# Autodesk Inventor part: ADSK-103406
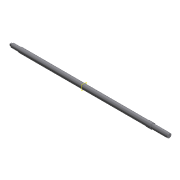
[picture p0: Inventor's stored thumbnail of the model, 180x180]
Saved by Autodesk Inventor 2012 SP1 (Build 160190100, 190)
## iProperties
Shininess: 0.0
Created: 2000-09
Part Number: ADSK-103406
Document SubType Name: Modeling
Stock Number: ADSK-103406
Density: 1 g/cm^3
Material: Default
Density: 0.0
Volumn: 0.0
Area: 0.0
PropertySet Name: Model Information
Control State: 0
Master: False
Checked Out: False
Author: gao
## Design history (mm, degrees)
node "Revolution1" dims "d20" = 360 deg
  sketch "Sketch1"
    geometry: L1 (-19.723, 10.363)-(1986.877, 10.363); L2 (1986.877, -26.943)-(-19.723, -26.943); L3 (-19.723, 4.807)-(-19.723, 10.363); L4 (1986.877, 10.363)-(1986.877, 14.332); L5 (1986.877, 14.332)-(2066.125, 14.332); L6 (2066.125, 14.332)-(2066.125, 8.057); L7 (2066.125, 8.057)-(2091.525, 8.057); L8 (2091.525, 8.057)-(2091.525, 7.855); L9 (2091.525, 7.855)-(2302.125, 7.855); L10 (2302.125, 7.855)-(2302.125, 5.557); L11 (2327.855, 5.557)-(2327.855, -26.943); L12 (1986.877, -26.943)-(2327.855, -26.943); L13 (2320.125, 5.557)-(2320.125, 4.057); L14 (2320.125, 4.057)-(2322.775, 4.057); L15 (2322.775, 4.057)-(2322.775, 5.557); L16 (2302.125, 5.557)-(2320.125, 5.557); L17 (2322.775, 5.557)-(2327.855, 5.557); L18 (-19.723, 4.807)-(-143.675, 4.807); L19 (-143.675, 4.807)-(-143.675, -26.943); L20 (-19.723, -26.943)-(-143.675, -26.943)
    constraints: 40 end point, 11 parallel, 8 perpendicular, 1 horizontal
    dimensions: "d1" = 37.30625 distance of L2.end L1.start; "d2" = 41.275 distance between parallel lines of L12 L5; "d4" = 79.248 distance of L4.end L5.end; "d5" = 25.4 distance of L6.end L7.end; "d6" = 35 distance between parallel lines of L12 L7; "d7" = 34.798 distance between parallel lines of L12 L9; "d9" = 32.5 distance between parallel lines of L12 L16; "d10" = 32.5 distance between parallel lines of L12 L17; "d11" = 31 distance between parallel lines of L12 L14; "d12" = 2.65 distance of L13.end L14.end; "d14" = 18 distance of L10.end L13.start; "d15" = 254 horizontal distance of L5.end L13.start; "d16" = 5.08 distance of L15.end L11.start; "d19" = 2006.6 distance of L1.start L1.end; "d27" = 31.75 distance between parallel lines of L20 L18; "d44" = 123.952 distance of L3.start L18.end
node "Extrusion1" dims "d25" = 28, "d26" = 0
  sketch "Sketch2"
    geometry: L1 (-15, 15)-(15, 15); L2 (15, 15)-(15, -15); L3 (15, -15)-(-15, -15); L4 (-15, -15)-(-15, 15); C1 r 31.75 at (0, 0) reference
    constraints: 8 end point, 2 parallel, 1 horizontal, 1 perpendicular
    dimensions: "d21" = 15 distance from line of C1.centre L4; "d22" = 30 distance of L2.end L3.end; "d23" = 30 distance of L1.end L2.end (= d22); "d24" = 15 distance from line of C1.centre L3 (= d21)
node "Fillet1" dims "d28" = 6.35
node "Chamfer1" dims "d29" = 1.524, "d30" = 1.524, "d46" = 45 deg
node "Fillet2" dims "d31" = 1.524
workplane "Work Plane1"
node "Hole1" dims "d33" = 6.4008, "d34" = 9.525, "d35" = 6.35, "d36" = 60 deg, "d37" = 19.05, "d38" = 118 deg, "d45" = 12.7
  sketch "Sketch3"
    geometry: C1 r 32.5 at (0, 0) reference; 1 further point
    constraints: 1 coincident
node "Chamfer2" dims "d39" = 1.524, "d40" = 1.524, "d47" = 45 deg
node "Fillet3" dims "d41" = 1.524
node "Fillet4" dims "d42" = 1.524
node "Fillet5" dims "d43" = 3.175
body "Solid1"
other parameters: "d8" = 32.5, "d32" = -1003.3 (= -0.5 x d19)
